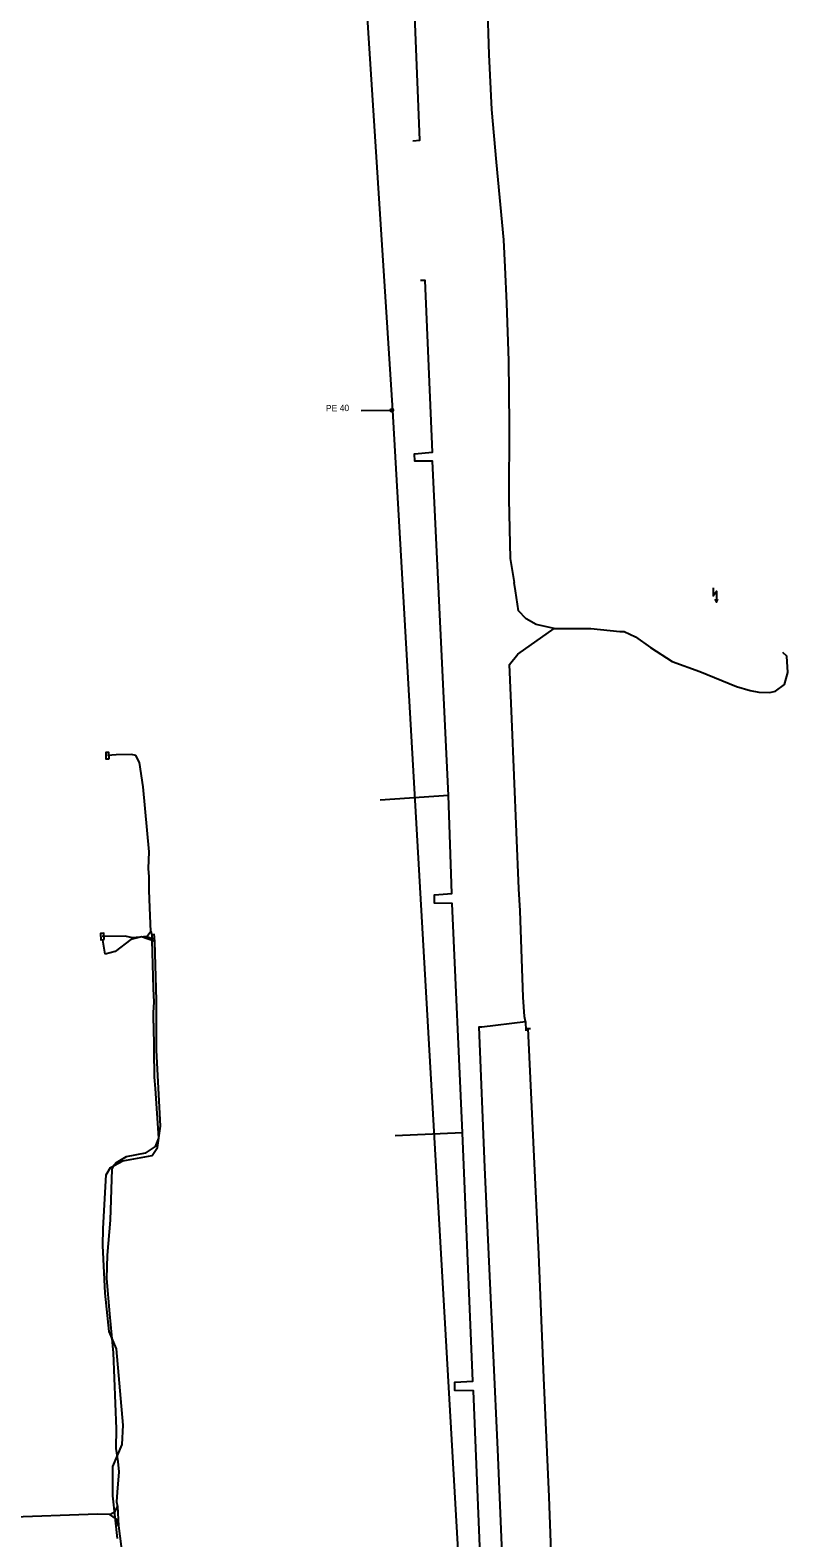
# Model space of a CAD drawing. Extents: x -736911 to -735381, y -1119567 to -1117933.
# Drawn here: x -736099.5 to -735980.6, y -1118803.9 to -1118567.4 of the extents above; entities that cross this region are included whole.
import ezdxf

# ---------------------------------------------------------------- set-up
doc = ezdxf.new("R2010")
doc.units = 0
for name, color, linetype in [('Kabelové skříně NN', 7, 'Continuous'), ('Kabelové vedení NN', 7, 'Continuous'), ('Kabelové vedení VN', 7, 'Continuous'), ('Nadz_ teplovodní potrubí', 7, 'Continuous'), ('Osa trasy kynety', 7, 'Continuous'), ('Popis vodovodních řadů', 7, 'Continuous'), ('Trafostanice_ rozvodny', 7, 'Continuous'), ('Vod přípojky-voda pitná', 7, 'Continuous'), ('Vodovodní řad', 7, 'Continuous'), ('Vodovodní šoupata', 7, 'Continuous')]:
    doc.layers.add(name, color=color, linetype=linetype)

msp = doc.modelspace()

# ---------------------------------------------------------------- linework, layer by layer
at = {"layer": 'Kabelové skříně NN'}
for points in [[(-736087.13, -1118681.69), (-736087.15, -1118680.69), (-736087.65, -1118680.69), (-736087.63, -1118681.69)], [(-736087.91, -1118710.05), (-736087.97, -1118709.05), (-736088.47, -1118709.07), (-736088.41, -1118710.07)]]:
    msp.add_lwpolyline(points, close=True, dxfattribs=at)
at = {"layer": 'Kabelové vedení NN'}
for points in [[(-736080.56, -1118708.79), (-736080.76, -1118705.08), (-736080.84, -1118702.28), (-736080.83, -1118700.22), (-736080.93, -1118698.91), (-736080.84, -1118696.3), (-736081.8, -1118686.07), (-736082.37, -1118682.29), (-736082.93, -1118681.19), (-736083.63, -1118681.03), (-736086.03, -1118681.09), (-736087.39, -1118681.19)], [(-736080.56, -1118708.79), (-736081.16, -1118709.54)], [(-736080.56, -1118708.79), (-736080.44, -1118709.32), (-736080.37, -1118710.2)], [(-736081.16, -1118709.54), (-736083.47, -1118709.77), (-736084.6, -1118709.52), (-736088.19, -1118709.56)], [(-736081.16, -1118709.54), (-736080.67, -1118709.79), (-736080.37, -1118710.2)], [(-736080.15, -1118723.16), (-736080.15, -1118721.5), (-736080.08, -1118719.84), (-736080.17, -1118717.73), (-736080.37, -1118710.2)], [(-736080.15, -1118723.16), (-736080.05, -1118731.6), (-736079.88, -1118733.39), (-736079.36, -1118741.18), (-736079.9, -1118742.51), (-736081.49, -1118743.55), (-736084.44, -1118744.12), (-736086.03, -1118745.06), (-736086.5, -1118745.61), (-736086.67, -1118746.03), (-736086.94, -1118754.05), (-736087.45, -1118759.53), (-736087.51, -1118763.22), (-736087.05, -1118768.74), (-736086.58, -1118773.77), (-736086.5, -1118774.88), (-736086.01, -1118786.79), (-736086.09, -1118789.86), (-736085.75, -1118791.92), (-736085.62, -1118793.54), (-736085.88, -1118796.7), (-736085.96, -1118798.21), (-736085.82, -1118798.97)], [(-736087, -1118800.2), (-736088.95, -1118800.15), (-736103.55, -1118800.69), (-736104.68, -1118799.76), (-736104.88, -1118798.93)], [(-736087, -1118800.2), (-736086.15, -1118799.76), (-736085.82, -1118798.97)], [(-736085.82, -1118798.97), (-736085.64, -1118801.99)], [(-736085.64, -1118801.99), (-736085.97, -1118800.92), (-736087, -1118800.2)], [(-736085.64, -1118801.99), (-736084.68, -1118809.67)]]:
    msp.add_lwpolyline(points, dxfattribs=at)
at = {"layer": 'Kabelové vedení VN'}
for points in [[(-736027.8, -1118562.99), (-736027.57, -1118571.22), (-736027.13, -1118579.88), (-736026.42, -1118588.12), (-736025.26, -1118600.31), (-736025.05, -1118604.61), (-736024.76, -1118610.23), (-736024.47, -1118619.3), (-736024.34, -1118629.26), (-736024.4, -1118640.97), (-736024.22, -1118650.28), (-736023.59, -1118654.03)], [(-736017.31, -1118661.25), (-736020.11, -1118660.65), (-736021.69, -1118659.76), (-736022.89, -1118658.51), (-736023.37, -1118655.38), (-736023.59, -1118654.03)], [(-736021.8, -1118722.89), (-736021.95, -1118722.13), (-736022.16, -1118719.07), (-736022.66, -1118705.52), (-736022.83, -1118702.1), (-736023.93, -1118675.43), (-736024.31, -1118666.89), (-736023.02, -1118665.28), (-736017.31, -1118661.25)], [(-736017.31, -1118661.25), (-736011.56, -1118661.26), (-736006.98, -1118661.73), (-736006.3, -1118661.74), (-736004.53, -1118662.55), (-736002.2, -1118664.25), (-735998.78, -1118666.45), (-735994.47, -1118668.02), (-735988.71, -1118670.34), (-735986.57, -1118670.99), (-735985.19, -1118671.26), (-735983.49, -1118671.31), (-735982.6, -1118671.07), (-735981.19, -1118670.07), (-735980.64, -1118668.15), (-735980.8, -1118665.59), (-735981.42, -1118665.05)], [(-736041.84, -1118825.03), (-736036.34, -1118824.87), (-736029.79, -1118824.67), (-736028.21, -1118824.34), (-736025.39, -1118822), (-736025.19, -1118821.7), (-736024.75, -1118820.27), (-736024.84, -1118819.57), (-736024.83, -1118819.07), (-736024.93, -1118817.61), (-736025.17, -1118814.15), (-736025.35, -1118808.76), (-736026.13, -1118790), (-736028.17, -1118745.81), (-736029.07, -1118723.75), (-736028.63, -1118723.75), (-736021.8, -1118722.89)], [(-736021.8, -1118722.89), (-736021.77, -1118724.35)], [(-736021.71, -1118723.97), (-736021.36, -1118723.97)], [(-736017.52, -1118813.2), (-736018.09, -1118797.43), (-736018.93, -1118778.77), (-736019.72, -1118759.4), (-736020.49, -1118742.98), (-736021.36, -1118723.97)], [(-736021.36, -1118723.97), (-736021.03, -1118723.98)]]:
    msp.add_lwpolyline(points, dxfattribs=at)
at = {"layer": 'Nadz_ teplovodní potrubí'}
for points in [[(-736039.45, -1118584.77), (-736038.35, -1118584.67), (-736040.53, -1118531.22), (-736041.79, -1118502.29), (-736044.01, -1118502.27), (-736044.06, -1118500.93), (-736041.78, -1118500.85), (-736042.53, -1118481.98), (-736056.09, -1118482.65)], [(-736033.89, -1118687.43), (-736036.37, -1118635), (-736039.18, -1118635.01), (-736039.22, -1118633.87), (-736036.38, -1118633.62), (-736037.52, -1118606.69), (-736038.27, -1118606.68)], [(-736050.59, -1118822.98), (-736028.62, -1118821.96), (-736028.54, -1118818.83), (-736028.77, -1118810.37), (-736029.97, -1118780.83), (-736032.89, -1118780.78), (-736032.88, -1118779.45), (-736030.07, -1118779.29), (-736031.67, -1118740.33), (-736033.3, -1118704.4), (-736036.07, -1118704.35), (-736036.09, -1118703.03), (-736033.38, -1118702.8), (-736033.89, -1118687.43), (-736044.6, -1118688.19)], [(-736031.67, -1118740.33), (-736042.25, -1118740.85)]]:
    msp.add_lwpolyline(points, dxfattribs=at)
at = {"layer": 'Osa trasy kynety'}
for points in [[(-736079.94, -1118710.35), (-736080.08, -1118709.13)], [(-736087.75, -1118712.36), (-736088.13, -1118710.14)], [(-736085.82, -1118804), (-736086.56, -1118797.26), (-736086.54, -1118792.66), (-736085.09, -1118789.23), (-736084.9, -1118786.2), (-736085.96, -1118774.23), (-736087.12, -1118771.52), (-736087.76, -1118765.52), (-736088.11, -1118758.05), (-736088.04, -1118755.38), (-736087.56, -1118746.94), (-736086.93, -1118745.78), (-736084.96, -1118744.75), (-736080.37, -1118743.93), (-736079.53, -1118742.66), (-736079.06, -1118739.29), (-736079.68, -1118727.39), (-736079.71, -1118719.61), (-736079.94, -1118710.35)], [(-736079.94, -1118710.35), (-736082.02, -1118709.64), (-736083.73, -1118710.02), (-736086.18, -1118711.94), (-736087.75, -1118712.36)]]:
    msp.add_lwpolyline(points, dxfattribs=at)
at = {"layer": 'Trafostanice_ rozvodny'}
for points in [[(-735992.36, -1118654.9), (-735992.36, -1118656.15), (-735991.86, -1118655.4), (-735991.86, -1118657.15)], [(-735992.11, -1118656.65), (-735991.86, -1118657.15), (-735991.61, -1118656.65)]]:
    msp.add_lwpolyline(points, dxfattribs=at)
at = {"layer": 'Vod přípojky-voda pitná'}
msp.add_lwpolyline([(-736042.59, -1118627.06), (-736042.77, -1118627.05), (-736047.59, -1118627.13)], dxfattribs=at)
at = {"layer": 'Vodovodní řad'}
msp.add_lwpolyline([(-736032.39, -1118806.17), (-736032.38, -1118805.78), (-736042.59, -1118627.06), (-736047.25, -1118554.85), (-736048.02, -1118518), (-736048.78, -1118490.59), (-736049.75, -1118479.86), (-736050.77, -1118460.86), (-736050.92, -1118436.47), (-736050.98, -1118424.63), (-736051.09, -1118410.02)], dxfattribs=at)
at = {"layer": 'Vodovodní šoupata'}
msp.add_circle((-736042.77, -1118627.05), 0.25, dxfattribs=at)

# ---------------------------------------------------------------- texts
at = {"layer": 'Popis vodovodních řadů'}
msp.add_text('PE 40', height=1, rotation=0.951, dxfattribs=at).set_placement((-736053.1, -1118627.23))

doc.saveas('drawing.dxf')
